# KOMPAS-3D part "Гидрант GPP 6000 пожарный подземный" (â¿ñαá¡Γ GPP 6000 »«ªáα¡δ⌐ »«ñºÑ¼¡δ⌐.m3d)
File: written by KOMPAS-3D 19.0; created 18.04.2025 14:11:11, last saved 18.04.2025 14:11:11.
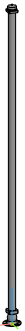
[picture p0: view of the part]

Document properties: Полное имя файла: E:\Dendor Работа Сачек\3D для проекитирвщиков\11.1 Тип GPP. Гидрант пожарный подземный\stp_Тип GPP. 750-6000 Гидрант пожарный подземный\Гидрант GPP 6000 пожарный подземный.m3d

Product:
- Part/product: Гидрант GPP 6000 пожарный подземный

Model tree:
1. Операция без истории:1  (labels: Гидрант GPP 6000 пожарный подземный)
